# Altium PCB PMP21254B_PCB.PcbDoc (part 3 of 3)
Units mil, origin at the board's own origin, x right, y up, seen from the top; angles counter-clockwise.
Board outline 5000 x 7000 mil, 8 copper layers (Top Layer, Signal Layer 1, Signal Layer 2, Signal Layer 3, Signal Layer 4, Signal Layer 5, Signal Layer 6, Bottom Layer), stack 63 mil thick; 205 components, 78 nets, 623 pads, 1087 vias.
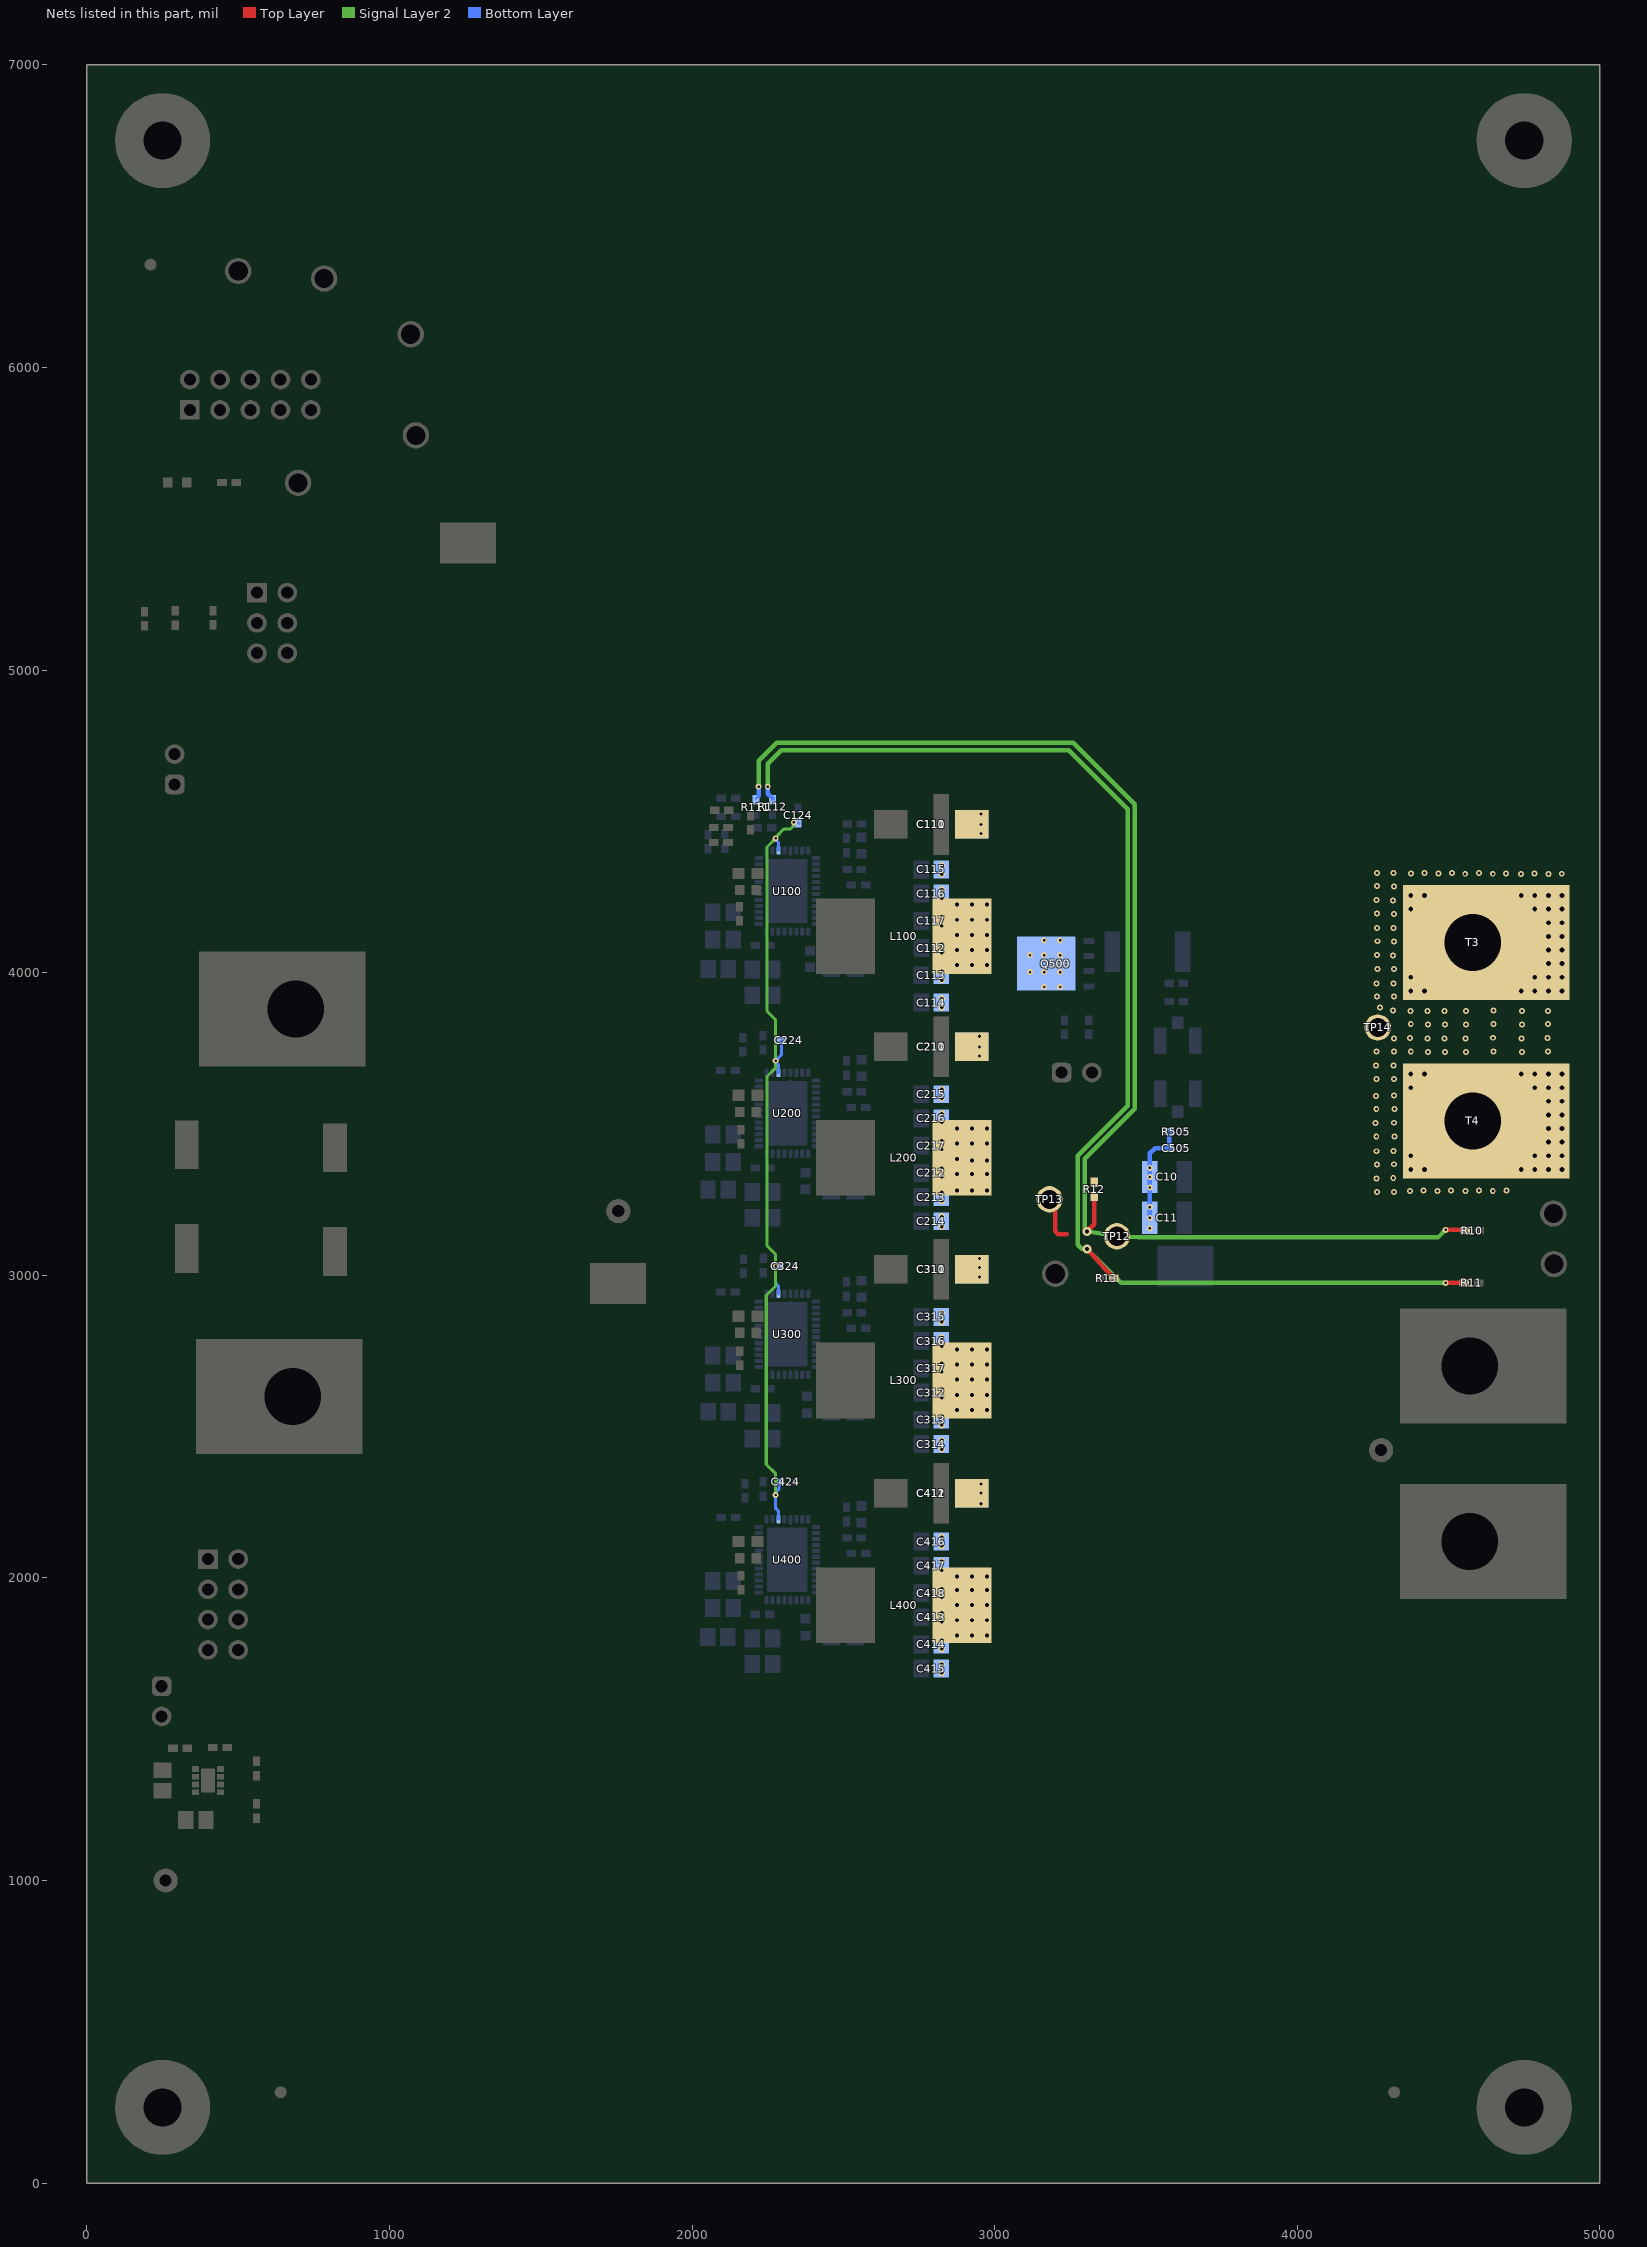
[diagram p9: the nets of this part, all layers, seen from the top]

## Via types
v1: diameter 19.68, hole 9.84, Top Layer to Bottom Layer, 427 vias
v2: diameter 22, hole 10, Top Layer to Bottom Layer, tented both sides, 225 vias
v3: diameter 30, hole 13, Top Layer to Bottom Layer, tented both sides, 171 vias
v4: diameter 32, hole 16, Top Layer to Bottom Layer, 168 vias
v5: diameter 19.68, hole 7.87, Top Layer to Bottom Layer, tented bottom, 35 vias
v6: diameter 19.68, hole 7.87, Top Layer to Bottom Layer, tented both sides, 27 vias
v7: diameter 19.68, hole 7.87, Top Layer to Bottom Layer, 22 vias
v8: diameter 22, hole 10, Top Layer to Bottom Layer, tented bottom, 6 vias
v9: diameter 19.68, hole 7.87, Top Layer to Bottom Layer, tented top, 5 vias
v10: diameter 19.68/19.68/19.68/19.68/19.68/19.68/19.68/19.68 (per signal layer), hole 7.87, Top Layer to Bottom Layer, tented both sides, 1 vias

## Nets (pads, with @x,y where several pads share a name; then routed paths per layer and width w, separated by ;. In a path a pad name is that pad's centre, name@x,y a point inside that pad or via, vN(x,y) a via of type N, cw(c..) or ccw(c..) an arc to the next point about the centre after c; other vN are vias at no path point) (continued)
Vout: C10.2 C11.2 C110.1 C111.1 C112.1 C113.1 C114.1 C115.1 C116.1 C117.1 C210.1 C211.1 C212.1 C213.1 C214.1 C215.1 C216.1 C217.1 C310.1 C311.1 C312.1 C313.1 C314.1 C315.1 C316.1 C317.1 C411.1 C412.1 C413.1 C414.1 C415.1 C416.1 C417.1 C418.1 C505.1 L100.2 L200.2 L300.2 L400.2 Q500.5 Q500.6 Q500.7 Q500.8 Q500.9@3170.09,4030 R12.1 R505.2 T3.1 T4.1 TP13.1 TP14.1 | length 445
  Top Layer w15: 3200,3210 3200,3145 3210,3135 3237.44,3135
  Bottom Layer w15: v5(3512.91,3190) v5(3512.91,3325) 3512.91,3402.91 3530,3420 C505.1@3576.38,3420 R505.2@3576.38,3475
  other v1: 4263.03,3275 4319.1,3276 4463,3278.03 4646,3278.03 4373,3279 4556,3279 4417,3280 4508,3280 4600,3280 4691,3280 4261.07,3320 4317.14,3321 4263.03,3366 4319.1,3367 4262.03,3410 4318.1,3411 4261,3458 4321,3459.1 4259.03,3503 4319.03,3504.1 4261,3549 4321,3550.1 4260,3593 4320,3594.1 4262,3648 4320,3648 4260.03,3693 4318.03,3693 4432,3738 4488,3738 4558,3738 4743,3738 4262,3739 4320,3739 4375,3739 4829,3739 4649,3740 4319,3783 4430.03,3783 4486.03,3783 4556.03,3783 4741.03,3783 4373.03,3784 4827.03,3784 4647.03,3785 4432,3829 4488,3829 4558,3829 4743,3829 4375,3830 4829,3830 4649,3831 4431,3873 4487,3873 4557,3873 4742,3873 4374,3874 4828,3874 4317.03,3875 4648,3875 4273,3885 4263,3921 4319,3921 4262,3965 4318,3965 4319,4012 4265,4013 4317.03,4057 4263.03,4058 4319,4103 4265,4104 4318,4147 4264,4148 4319,4194 4264,4195 4317.03,4239 4262.03,4240 4319,4285 4264,4286 4739,4326 4830,4326 4555,4326.97 4646,4326.97 4874,4327 4376,4327.93 4467,4327.93 4690,4327.97 4784,4327.97 4318,4329 4511,4328.93 4600,4328.93 4263,4330 4421,4329.9
  other v2: 2825,1685 2825,1715 2825,1765 2825,1795 2825,1855 2825,1885 2825,1935 2825,1965 2825,2025 2825,2055 2825,2105 2825,2135 2955,2245 2955,2280 2955,2310 2825,2425 2825,2455 2825,2505 2825,2535 2825,2595 2825,2625 2825,2680 2825,2710 2825,2765 2825,2795 2825,2845 2825,2875 2950,2995 2950,3025 2950,3055 2825,3160 2825,3195 2825,3245 2825,3275 2825,3325 2825,3355 2825,3415 2825,3445 2825,3505 2825,3535 2825,3585 2825,3615 2950,3725 2950,3755 2950,3790 2825,3885 2825,3915 2825,3975 2825,4005 2825,4065 2825,4095 2825,4155 2825,4185 2825,4245 2825,4275 2825,4325 2825,4355 2955,4460 2955,4490 2955,4525
  other v3: 2875,1810 2925,1810 2975,1810 2875,1860 2925,1860 2975,1860 2875,1910 2925,1910 2975,1910 2875,1960 2925,1960 2975,1960 2875,2005 2925,2005 2975,2005 2875,2555 2925,2555 2975,2555 2875,2605 2925,2605 2975,2605 2875,2655 2925,2655 2975,2655 2875,2705 2925,2705 2975,2705 2875,2755 2925,2755 2975,2755 2875,3280 2925,3280 2975,3280 2875,3335 2925,3335 2975,3335 2925,3380 2975,3380 2875,3385 2875,3435 2925,3435 2975,3435 2875,3485 2925,3485 2975,3485 2875,4025 2925,4025 2975,4025 2875,4075 2925,4075 2975,4075 2875,4125 2925,4125 2975,4125 2875,4175 2925,4175 2975,4175 2875,4225 2925,4225 2975,4225
  other v4: 4375,3350 4420,3350 4740,3350 4785,3350 4830,3350 4875,3350 4375,3395 4785,3395 4830,3395 4875,3395 4830,3440 4875,3440 4830,3485 4875,3485 4830,3530 4875,3530 4830,3575 4875,3575 4375,3620 4785,3620 4830,3620 4875,3620 4375,3665 4420,3665 4740,3665 4785,3665 4830,3665 4875,3665 4375,3940 4420,3940 4740,3940 4785,3940 4830,3940 4875,3940 4375,3985 4785,3985 4830,3985 4875,3985 4830,4030 4875,4030 4830,4075 4875,4075 4830,4120 4875,4120 4830,4165 4875,4165 4375,4210 4785,4210 4830,4210 4875,4210 4375,4255 4420,4255 4740,4255 4785,4255 4830,4255 4875,4255
  other v5: 3512.91,3155 3512.91,3225 3512.91,3290 3512.91,3355
  other v7: 3163.62,3952.83 3216.38,3952.83 3116.77,4001.85 3163.62,4001.85 3216.38,4001.85 3116.77,4058.15 3163.62,4058.15 3216.38,4058.15 3163.62,4107.17 3216.38,4107.17
VSH: C124.1 C224.1 C324.1 C424.1 U100.35 U200.35 U300.35 U400.35 | length 2728
  Signal Layer 2 w10: v5(2276,2274) 2276,2344 2245,2375 2245,2933.43 2276,2964.43 v5(2276,3030) 2276,3069 2247.13,3097.87 2247.13,3657.13 2276,3686 v7(2276,3709) 2276,3844 2247.13,3872.87 2247.13,4415.13 v7(2276,4444) 2276,4448.13 2302.87,4475 2325,4475 2336,4486 v5(2336,4497)
  Bottom Layer w10: v5(2276,3030) 2276,2974 2285.47,2964.53 U300.35@2285.47,2938.86 ; v7(2276,4444) 2276,4439.87 2285.47,4430.4 U100.35@2285.47,4403.86 ; U400.35@2285.47,2193.86 2285.47,2220.4 2276,2229.87 v5(2276,2274) 2276,2283 2286.38,2293.38 C424.1@2286.38,2317 ; U200.35@2285.47,3668.86 2285.47,3695.4 2276,3704.87 v7(2276,3709) 2295,3728 C224.1@2295,3776 ; C124.1@2350,4496.38 C124.1@2353,4493.38
VSNS_N: R11.2 R13.2 R112.1 | length 4376.2
  Top Layer w15: v3(3305,3087.56) R13.2@3393.62,2990 ; R13.2@3397.56,2990 R13.2@3397.56,2995 ; v9(4490,2975) R11.2@4543.5,2975
  Signal Layer 2 w15: v6(2250,4615) 2250,4690 2295,4735 3245,4735 3440,4540 3440,3560 3274.63,3394.63 3274.63,3100.37 3287.44,3087.56 v3(3305,3087.56) 3417.56,2975 v9(4490,2975)
  Bottom Layer w15: v6(2250,4615) 2250,4591.56 R112.1@2266,4575.56
VSNS_P: R10.1 R12.2 R111.1 TP12.1 | length 4389.2
  Top Layer w15: v3(3305,3145) 3329,3169 R12.2@3329,3260.86 ; TP12.1@3380,3115 TP12.1@3415,3150 ; v9(4490,3150) R10.1@4543.5,3150
  Signal Layer 2 w15: v6(2220,4615) 2220,4700 2280,4760 3260,4760 3462.87,4557.13 3462.87,3550.53 3297.5,3385.15 3297.5,3152.5 v3(3305,3145) TP12.1@3404,3129 3475,3125 4465,3125 v9(4490,3150)
  Bottom Layer w10: R111.1@2211,4575.56 R111.1@2220,4584.56
  Bottom Layer w15: R111.1@2220,4584.56 v6(2220,4615)
pads on no net: FID1.1 FID2.1 FID3.1 H1.1 H2.1 H3.1 H4.1 H5.0 H6.0 H7.0 H8.0 J2.1 J2.2 J2.3 J2.4 J500.2@3545.94,3775 J500.3@3664.06,3775 J501.2@3664.06,3600 J501.3@3545.94,3600 LBL1.0 Q500.9@3137.24,3973.7 Q500.9@3137.24,4030 Q500.9@3137.24,4086.3 Q500.9@3186.06,4030 Q500.9@3190,3973.7 Q500.9@3190,4030 Q500.9@3190,4086.3 Q500.9@3242.76,3973.7 Q500.9@3242.76,4030 Q500.9@3242.76,4086.3 U1.0 U1.7 U100.41@2282.91,4194.41 U100.41@2282.91,4244.8 U100.41@2282.91,4295.2 U100.41@2282.91,4345.59 U100.41@2347.09,4194.41 U100.41@2347.09,4244.8 U100.41@2347.09,4295.2 U100.41@2347.09,4345.59 U200.33 U200.41@2282.91,3459.41 U200.41@2282.91,3509.8 U200.41@2282.91,3560.2 U200.41@2282.91,3610.59 U200.41@2347.09,3459.41 U200.41@2347.09,3509.8 U200.41@2347.09,3560.2 U200.41@2347.09,3610.59 U300.33 U300.41@2282.91,2729.41 U300.41@2282.91,2779.8 U300.41@2282.91,2830.2 U300.41@2282.91,2880.59 U300.41@2347.09,2729.41 U300.41@2347.09,2779.8 U300.41@2347.09,2830.2 U300.41@2347.09,2880.59 U400.33 U400.41@2282.91,1984.41 U400.41@2282.91,2034.8 U400.41@2282.91,2085.2 U400.41@2282.91,2135.59 U400.41@2347.09,1984.41 U400.41@2347.09,2034.8 U400.41@2347.09,2085.2 U400.41@2347.09,2135.59
copper on no net:
  other v2: 3230,2205 3230,2310 1090,2645 1090,2780

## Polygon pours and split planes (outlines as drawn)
GND on Signal Layer 1 "SIGNAL_LAYER_1_GND_P027" (solid, remove dead copper, pour order 27): 0,-25 0,7010 4955,7010 4990,6975 4990,10
GND on Signal Layer 3 "SIGNAL_LAYER_3_GND_P031" (solid, remove dead copper, pour order 31): -25,0 -25,6960 25,7010 4975,7010 4975,25 5000,0
GND on Signal Layer 6 "SIGNAL_LAYER_6_GND_P041" (solid, remove dead copper, pour order 41): 10,25 0,35 0,7000 5010,7000 4975,6965 4975,-10
Vout on Signal Layer 4 "SIGNAL_LAYER_4_VOUT_P035" (solid, remove dead copper, pour order 35): 5000,977 5000,5176 2800,5176 2800,977
Vin on Signal Layer 4 "SIGNAL_LAYER_4_VIN_P051" (solid, remove dead copper, pour order 51): 0,1305 2215,1305 2215,5160 0,5160 0,3220 0,2355
GND on Signal Layer 4 "SIGNAL_LAYER_4_GND_P053" (solid, remove dead copper, pour order 53): 0,7000 5000,7000 5000,0 0,0 0,1275 2250,1275 2250,4900 0,4900
Vout on Top Layer "TOP_LAYER_VOUT_P023" (solid, remove dead copper, pour order 23): 2790,1655 2790,2160 2862.48,2160 2862.48,2397.48 2785,2397.48 2785,2907.32 2855,2907.32 2855,3140 2775,3140 2775,3643.44 2845,3643.44 2845,3870 2790,3870 2790,4374.92 2862.48,4374.92 2862.48,4600 3050,4600 3050,1655
Vout on Top Layer "TOP_LAYER_VOUT_P025" (solid, remove dead copper, pour order 25): 4997.69,999 4997.69,5171 2787.69,5171 2787.69,999
Vin on Top Layer "TOP_LAYER_VIN_P045" (solid, remove dead copper, pour order 45): -1.28,1306.06 2213.72,1306.06 2213.72,5161.06 -1.28,5161.06 -1.28,3221.06 1198.72,3221.06 1198.72,2356.06 -1.28,2356.06
GND on Top Layer "TOP_LAYER_GND_P047" (solid, remove dead copper, pour order 47): 0,2375 1175,2375 1175,3200 0,3200
GND on Top Layer "TOP_LAYER_GND_P055" (solid, remove dead copper, pour order 55): 0,7005 5000,7005 5000,0 0,0 0,1280 2250,1280 2250,4905 0,4905
Vout on Signal Layer 5 "SIGNAL_LAYER_5_VOUT_P039" (solid, remove dead copper, pour order 39): 5000,977 5000,5182 2800,5182 2800,977
Vin on Signal Layer 5 "SIGNAL_LAYER_5_VIN_P037" (solid, remove dead copper, pour order 37): 190,4460 1245,4460 2215,4460 2215,1325 190,1325 190,3230
GND on Signal Layer 5 "SIGNAL_LAYER_5_GND_P049" (solid, remove dead copper, pour order 49): 0,7000 5000,7000 5000,0 0,0 0,1275 2250,1275 2250,4900 0,4900
GND on Bottom Layer "BOTTOM_LAYER_GND_P043" (solid, remove dead copper, pour order 43): 5155.09,28.16 5155.09,7033.16 155.09,7033.16 155.09,28.16
GND on Signal Layer 2 "SIGNAL_LAYER_2_GND_P057" (solid, remove dead copper, pour order 57): 5000,0 5000,7005 0,7005 0,0

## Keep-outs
Keep-Out Layer:
  lines w20: -10,0 ccw(c0,0) 0,-10 ; -10,0 ccw(c0,0) 0,-10 ; -10,0 -10,7000 ; -10,7000 cw(c0,7000) 0,7010 ; -10,7000 cw(c0,7000) 0,7010 ; 0,-10 5000,-10 ; 0,7010 5000,7010 ; 5000,-10 ccw(c5000,0) 5010,0 ; 5000,-10 ccw(c5000,0) 5010,0 ; 5000,7010 cw(c5000,7000) 5010,7000 ; 5000,7010 cw(c5000,7000) 5010,7000 ; 5010,0 5010,7000 ; 10,10 4990,10 4990,6990 10,6990 10,10 ; 26.23,26.23 26.23,6973.77 4973.77,6973.77 4973.77,26.23 26.23,26.23
  text ".Layer_Name" at 577,-858.49 h60

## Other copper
Top Layer:
  rectangle net 5.3V: 363,1155 465,1270
  rectangle net GND: 2197,4304 2275,4393.88
  rectangle net GND: 2200,3577 2282,3613
  rectangle net GND: 2201,2849 2265,2882.58
  rectangle net GND: 2198,2102.26 2275,2137.85
  text ".Layer_Name" at 577,-858.49 h60
Signal Layer 6:
  rectangle net GND: 2260.39,1942 2383,2078
  rectangle net GND: 2260.47,2702.4 2295,2785
  rectangle net GND: 2266,4145 2372,4230.49
  rectangle net GND: 2250.45,3435 2275,3499.01
  rectangle net GND: 2034.8,4075 2172.72,4235
  rectangle net GND: 2035,3335.63 2170,3503.1
  rectangle net GND: 2035,2610 2169.65,2770
  rectangle net GND: 2032.52,1870 2170,2029.37
Bottom Layer:
  rectangle net GND: 2245,1905 2385,1960
  rectangle net GND: 2246.1,2650 2383.9,2705
  rectangle net GND: 2246.1,3376 2383.9,3440
  rectangle net GND: 2245,4120 2383.57,4175
  rectangle net Vout: 3485,3220 3540,3320
  rectangle net Vout: 2795,3870 3265,4375
  rectangle net NetC500_1: 3295,3995 3415,4135.94
  rectangle net NetC422_2: 2511,2170 2548,2199
  rectangle net F3_BP1V5: 2515,2222 2551,2249
  rectangle net L_BP1V5: 2510,4430 2555,4460
  rectangle net F1_BP1V5: 2510,3697 2549,3728
  rectangle net F2_BP1V5: 2515,2970 2550,2995
  rectangle net NetC109_1: 2370,3975 2579.37,4040
  rectangle net NetC209_1: 2360,3240 2574.37,3305
  rectangle net NetC309_1: 2360,2505 2575,2570
  region net Vin: 2230,4245 2110,4245 2110,4070 2094.92,4054.92 2094.92,3885 2230,3885
  region net Vin: 2230,3510 2230,3160 2228.52,3158.52 2090,3158.52 2090,3240 2104.45,3240 2104.45,3326.62 2104.45,3507.34 2105,3507.89
  region net Vin: 2230,2780 2230,2423.03 2104,2423.03 2104,2429 2104,2502.4 2104,2780
  region net GND: 2405.06,1885 2405.06,1840 2345,1840 2345,1680 2240,1680 2240,1885
  region net GND: 2400,2630 2400,2580 2350,2580 2350,2415 2240,2415 2240,2630
  region net GND: 2390,3365 2390,3320 2345,3320 2345,3160 2240,3160 2240,3365
  region net GND: 2410,4095 2410,4055 2355,4055 2355,3890 2245,3890 2245,4095
  region net NetC408_2: 2605,2035 2605,1840 2415,1840 2416.38,1841.38 2416.38,1950 2400,1950 2400,2035
  region net NetC308_2: 2400,2780 2605,2780 2605,2580 2416.38,2580 2416.38,2690 2400,2690
  region net NetC208_2: 2399.68,3510 2604.68,3510 2604.68,3315 2405.31,3315 2405.31,3425.26 2399.94,3425.26
  region net NetC108_2: 2398.64,4240 2605,4240 2605,4050 2420,4050 2420,4160 2400.62,4160
  region net Vin: 2230,2035 2230,1680.63 2229.37,1680 2110,1680 2110,1759.37 2110,1849.37 2110,2035
  text ".Layer_Name" at 577,-858.49 h60

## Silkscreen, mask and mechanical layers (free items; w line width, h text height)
Top Overlay:
  region: 2682,343 2382,343 2382,243 2682,243
  lines w10: 3000,1600 2000,1600 2000,4600 3000,4600 3000,1610
  text "Gnd" at 400,6240 h72.83 r90
  text "SMB_ALERT" at 670,6210 h72.83 r90
  text "PMBus Communications" at 180,6120 h72.83
  text "DATA" at 1012,5975 h72.83
  text "CLK" at 1020,5860 h72.83
  text "Cntl" at 800,5620 h72.83
  text "GND" at 1389,5411 h72.83
  text "Enable Choices" at 613,5339 h72.83
  text "PMBus CNTL" at 730,5240 h72.83
  text "UVLO" at 738,5107.63 h72.83
  text "UVLO divider" at 80,5050 h72.83
  text "Off" at 736,5026 h72.83
  text "All parts outside box are Test Interface" at 1820,4810 h110
  text "Actual design inside 1 inch by 4 inch box" at 1730,4720 h120
  text "Power Good" at 381,4698 h90
  text "Gnd" at 364,4590 h72.83
  text "Vin +" at 500,4140 h180
  text "Leader" at 1342,4089 h150
  text "Vout" at 4310,3980 h150 r90
  text "VOUT" at 4346,3791 h90
  text "Follower_1" at 1349,3524.97 h100
  text "Main Load +" at 4170,3415 h180 r90
  text "Vout" at 4310,3410 h150 r90
  text "Bode_Vout" at 3052,3344 h72.83
  text "RemoteSense+" at 4299,3208 h72.83
  text "VIN" at 1579,3191 h72.83
  text "Bode_Injection" at 3484,3083.47 h72.83
  text "RemoteSense-" at 4305,3030 h72.83
  text "GND" at 1494,2952.92 h72.83
  text "damping input caps" at 230,2890 h90
  text "Bode_Gnd" at 3045,2885 h72.83
  text "Follower_2" at 1388,2634 h100
  text "Ground" at 4300,2490 h150 r90
  text "GND" at 4346,2362 h90
  text "Vin Return" at 129,2244 h150
  text "---5.3V----" at 273,2085 h90 r270
  text "avin_l" at 580,2050 h72.83
  text "avin_f1" at 580,1940 h72.83
  text "Ground" at 4320,1910 h150 r90
  text "Main Load Rtn" at 4170,1900 h180 r90
  text "Follower_3" at 1405,1892 h100
  text "avin_f2" at 570,1840 h72.83
  text "avin_f3" at 570,1740 h72.83
  text "Bias Enable (5.3V)" at 331.49,1577 h90
  text "A" at 1570,1463.66 h182.5
  text "c" at 1658.24,1463.66 h182.5
  text "t" at 1723.18,1463.66 h182.5
  text "u" at 1774.79,1463.66 h182.5
  text "a" at 1854.71,1463.66 h182.5
  text "l" at 1927.97,1463.66 h182.5
  text "d" at 1997.9,1463.66 h182.5
  text "e" at 2077.82,1463.66 h182.5
  text "s" at 2154.41,1463.66 h182.5
  text "i" at 2214.35,1463.66 h182.5
  text "g" at 2249.32,1463.66 h182.5
  text "n" at 2320.91,1463.66 h182.5
  text "i" at 2435.8,1463.66 h182.5
  text "n" at 2470.76,1463.66 h182.5
  text "s" at 2550.68,1463.66 h182.5
  text "i" at 2610.62,1463.66 h182.5
  text "d" at 2645.59,1463.66 h182.5
  text "e" at 2725.51,1463.66 h182.5
  text "1" at 2835.4,1463.66 h182.5
  text "i" at 2948.62,1463.66 h182.5
  text "n" at 2983.58,1463.66 h182.5
  text "c" at 3063.5,1463.66 h182.5
  text "h" at 3128.44,1463.66 h182.5
  text "b" at 3241.66,1463.66 h182.5
  text "y" at 3321.58,1463.66 h182.5
  text "4" at 3426.47,1463.66 h182.5
  text "i" at 3539.69,1463.66 h182.5
  text "n" at 3574.65,1463.66 h182.5
  text "c" at 3654.57,1463.66 h182.5
  text "h" at 3719.51,1463.66 h182.5
  text "b" at 3832.73,1463.66 h182.5
  text "o" at 3912.65,1463.66 h182.5
  text "x" at 3994.23,1463.66 h182.5
  text "5.3V" at 347,960 h90
  text "Vin to 5.3V converter" at 70,820 h120
  text "'.PRJ_Number'.PCB_Rev-" at 1791,264 h108.27
  text ".Layer_Name" at 577,-858.49 h60
Bottom Overlay:
  lines w10: 2990,1600 2000,1600 2000,4600 3000,4600 3000,1600
  text "All parts outside box are Test Interface" at 3355,5040 h110
  text "Actual design inside 1 inch by 4 inch box" at 3518,4935 h120
  text "Isense" at 3887,3783 h80
  text "sig injection" at 3435,3729 h72.83 r90
  text "Vsense" at 3904,3600 h72.83
  text "GND" at 3814,3094.23 h72.83 r90
  text "Actual design inside 1 inch by 4 inch box" at 3530,1490 h120
  text ".Layer_Name" at 577,-858.49 h60
Top Paste:
  text ".Layer_Name" at 577,-858.49 h60
Bottom Paste:
  text ".Layer_Name" at 577,-858.49 h60
Top Solder:
  text ".Layer_Name" at 577,-858.49 h60
  text ".Layer_Name" at 577,-858.49 h60
Bottom Solder:
  text ".Layer_Name" at 577,-858.49 h60
Drill Guide:
  text ".Layer_Name" at 577,-858.49 h60
M1 Board Outline:
  the board outline again, w10
  text ".Layer_Name" at 577,-858.49 h60
M2 Board Dimensions:
  rectangle: 125,-400 500,-275
  rectangle: 0,-275 125,-150
  lines w7: 0,-275 1000,-275 ; 125,-400 125,-150 ; 250,-400 250,-150 ; 500,-400 500,-150 ; 750,-400 750,-150 ; 0,-400 0,-150 1000,-150 1000,-400 0,-400
  text ".Layer_Name" at 577,-858.49 h60
M3 3D STEP Top:
  text ".Layer_Name" at 577,-858.49 h60
M4 3D STEP Bottom:
  text ".Layer_Name" at 577,-858.49 h60
M5 Assembly Top:
  lines w10: -292,-930.17 6308,-930.17 ; -292,-726.83 6310,-726.83 ; -292,-523.5 -292,-1133.5 3713,-1133.5 6310,-1133.5 6310,-523.5 -291.5,-523.5 -291.5,-1133.5 1284,-1133.5 ; 2173,-1133.5 2173,-523.5 ; 3440,-726.83 3440,-523.5 ; 4280,-726.83 4280,-523.5 ; 4902,-1140 4902,-937.17
  text "COMPONENTS MARKED 'DNP' SHOULD NOT BE POPULATED." at 1153.5,-318.5 h60
  text "ASSEMBLY VARIANT:" at 1153,-434 h60
  text ".VariantName" at 2189,-434 h60
  text "PCB VIEWED FROM TOP SIDE" at -228.5,-655.67 h60
  text "BOARD #:" at 2248,-655.67 h60
  text ".PRJ_Number" at 2793.5,-655.67 h60
  text "REV:" at 3638,-655.67 h60
  text ".PCB_Rev" at 3929.5,-655.67 h60
  text "SVN REV:" at 4476,-655.67 h60
  text ".VersionControl_RevNumber" at 4982,-655.67 h60
  text "TID #:" at 2248,-859 h60
  text ".TID" at 2793.5,-859 h60
  text "PLOT NAME =" at -228.5,-1064.34 h60
  text ".plot_File_Name" at 577,-1064.34 h60
  text "GENERATED    :" at 2250,-1064.34 h60
  text ".Print_Date" at 3119.5,-1064.34 h60
  text ".Print_Time" at 3848.5,-1064.34 h60
  text "TEXAS INSTRUMENTS" at 5113,-1064.34 h60
M6 Assembly Bottom:
  lines w10: -292.5,-727.33 6309.5,-727.33 ; -290.5,-930.67 6309.5,-930.67 ; 1115.5,-1140.5 1115.5,-937.67 ; 1737.5,-727.33 1737.5,-524 ; 2577.5,-727.33 2577.5,-524 ; 3844.5,-1134 3844.5,-524 ; 4733.5,-1134 6309,-1134 6309,-524 -292.5,-524 -292.5,-1134 2304.5,-1134 6309.5,-1134 6309.5,-524
  text "COMPONENTS MARKED 'DNP' SHOULD NOT BE POPULATED." at 6102,-318 h60
  text ".VariantName" at 5058,-434 h60
  text "ASSEMBLY VARIANT:" at 6097,-434 h60
  text ".VersionControl_RevNumber" at 1035.5,-656.17 h60
  text "SVN REV:" at 1541.5,-656.17 h60
  text ".PCB_Rev" at 2088,-656.17 h60
  text "REV:" at 2379.5,-656.17 h60
  text ".PRJ_Number" at 3224,-656.17 h60
  text "BOARD #:" at 3769.5,-656.17 h60
  text "PCB VIEWED FROM BOTTOM SIDE" at 6246,-656.17 h60
  text ".TID" at 3224,-859.5 h60
  text "TID #:" at 3769.5,-859.5 h60
  text "TEXAS INSTRUMENTS" at 904.5,-1064.84 h60
  text ".Print_Time" at 2169,-1064.84 h60
  text ".Print_Date" at 2898,-1064.84 h60
  text "GENERATED    :" at 3767.5,-1064.84 h60
  text ".plot_File_Name" at 5440.5,-1064.84 h60
  text "PLOT NAME =" at 6246,-1064.84 h60
M9 Title Sheet:
  drawing of 57 lines, arcs and shapes, not listed
  text "1" at 739.84,8036.5 h70
  text "2" at 3235.5,8036.5 h70
  text "3" at 5724.84,8036.5 h70
  text "4" at 8231.51,8036.5 h70
  text "5" at 10730.5,8036.5 h70
  text "6" at 13235.5,8036.5 h70
  text "A" at -416.5,6893.5 h70
  text "A" at 14383.5,6893.5 h70
  text "B" at -416.5,4513.5 h70
  text "B" at 14383.5,4513.5 h70
  text "C" at -416.5,2138.5 h70
  text "C" at 14383.5,2138.5 h70
  text "PROJECT TITLE:" at 11343.5,277.5 h45
  text ".PRJ_Title" at 11393.5,144.17 h70
  text "DESIGNED FOR:" at 11343.5,-23.5 h45
  text ".PRJ_Customer" at 11393.5,-163.5 h70
  text "D" at -416.5,-231.5 h70
  text "D" at 14383.5,-231.5 h70
  text "FILE NAME:" at 11343.5,-323.5 h45
  text ".PCB_File_Name_No_Path" at 11393.5,-443.5 h70
  text "Texas Instruments (TI) and/or its licensors do not warrant the accuracy or completeness of this specification" at 6374,-605.34 h45
  text "ENGINEER:" at 11343.5,-613.5 h45
  text "LAYOUT BY:" at 12848.5,-613.5 h45
  text "or any information contained therein. TI and/or its licensors do not warrant that this design will meet" at 6329.01,-718 h45
  text ".PRJ_Engineer" at 11393.5,-768.49 h70
  text ".PCB_Layout" at 12899,-768.49 h70
  text "the specifications, will be suitable for your application or fit for any particular purpose, or will operate in" at 6329.01,-830.67 h45
  text ".Layer_Name" at 577,-858.49 h60
  text "ALTIUM DESIGNER VERSION:" at 12848.5,-923.5 h45
  text "an implementation. TI and/or its licensors do not warrant that the design is production worthy. You should" at 6329.01,-943.33 h45
  text "completely validate and test your design implementation to confirm the system functionality for your application." at 6374,-1056 h45
  text ".print_Scale" at 11393.5,-1056.83 h70
  text ".Application_BuildNumber" at 12899,-1056.83 h70
  text "1" at 739.84,-1263.5 h70
  text "2" at 3235.5,-1263.5 h70
  text "3" at 5724.84,-1263.5 h70
  text "4" at 8231.51,-1263.5 h70
  text "5" at 10730.5,-1263.5 h70
  text "6" at 13235.5,-1263.5 h70
M10 Fab Notes:
  drawing of 189 lines, arcs and shapes, not listed
  text "DESIGN INFORMATION" at 12382.02,6356.17 h60
  text "MIN. TRACK WIDTH:" at 11737.46,6224.05 h60
  text "8" at 12833.7,6224.05 h60
  text "MIL" at 12988.46,6224.05 h60
  text "5.906" at 12665,6105 h60
  text "MIN. CLEARANCE:" at 11737.46,6099.92 h60
  text "MIL" at 12988.46,6099.92 h60
  text "MIN. VIA PAD SIZE:" at 11737.46,5975.8 h60
  text "24" at 12803.71,5975.8 h60
  text "MIL" at 12988.46,5975.8 h60
  text "0.05mm (2MIL)" at 12432.46,5845.9 h60
  text "MINIMUM ANNULAR RING" at 11408.23,5837.67 h60
  text "EXTERNAL" at 13140.46,5837.67 h60
  text "PER" at 11608.23,5727.55 h60
  text "IPC-D-275 CLASS 2 LEVEL C" at 11828.23,5727.54 h60
  text "MIL, HOLES" at 13316.46,5627.07 h60
  text "+/-" at 12924,5618.48 h60
  text "+/-" at 13778,5618.48 h60
  text "REGISTRATION TOLERANCES:" at 11408.23,5617.42 h60
  text "METAL" at 12608,5617.42 h60
  text "5" at 13184.2,5617.42 h60
  text "3" at 14017.2,5617.42 h60
  text "MIL" at 14133.46,5617.42 h60
  text "HOLE SIZE TOLERANCE (UNLESS OTHERWISE SPECIFIED):" at 11408.23,5519.1 h60
  text "+/-" at 13778,5516.23 h60
  text "3" at 14017.2,5515.17 h60
  text "MIL" at 14133.46,5515.17 h60
  text "MATERIAL:" at 11333.46,5377.52 h60
  text "FR-4 High Tg" at 12319.9,5249 h60
  text "X" at 12175.46,5241.01 h60
  text "FR-408" at 11754.46,5236.49 h60
  text "OTHER" at 13242.46,5236.49 h60
  text "62 MIL (1.6mm) +/-10%" at 12074.56,5093.46 h60
  text "X" at 11954.46,5091.01 h60
  text "THICKNESS:" at 11408.23,5085.24 h60
  text "OTHER" at 13359.46,5085.24 h60
  text "TOLERANCE:" at 11408.23,4946.92 h60
  text "X" at 12256.46,4946.92 h60
  text "ANSI IPC-6012 TYPE 3 CLASS 2" at 12434.48,4946.92 h60
  text "OTHER +/-" at 12434.46,4802.73 h60
  text "BOW & TWIST:" at 11408.23,4657.54 h60
  text "X" at 12256.46,4657.54 h60
  text "ANSI IPC-6012 TYPE 3 CLASS 2" at 12434.48,4657.54 h60
  text "OTHER +/-" at 12434.46,4510.85 h60
  text "DRILLING:" at 11333.46,4380.23 h60
  text "NC_DRILL FILES" at 13094.46,4275.04 h60
  text "REFERENCE:" at 11408.23,4271.1 h60
  text "X" at 12065.46,4271.01 h60
  text "AS SHOWN" at 12243.46,4271.1 h60
  text "X" at 12966.46,4271.1 h60
  text "OTHER" at 13392.46,4128.85 h60
  text "PTH COPPER THICKNESS:" at 11407.91,4125.32 h60
  text "X" at 12547.14,4125.32 h60
  text "20-30 um" at 12675.14,4125.32 h60
  text "BOARD FINISH:" at 11333.46,3977.73 h60
  text "SILKSCREEN:" at 11488.68,3867.6 h60
  text "X" at 12446.46,3867.6 h60
  text "TOP" at 12563.46,3867.6 h60
  text "X" at 12956.46,3867.6 h60
  text "BOTTOM" at 13074.46,3867.6 h60
  text "SILKSCREEN COLOR:" at 11488.68,3712.41 h60
  text "X" at 12445.46,3712.41 h60
  text "WHITE" at 12563.46,3712.41 h60
  text "OTHER" at 13074.46,3712.41 h60
  text "X" at 12576.46,3568.96 h60
  text "GREEN" at 12694.46,3568.96 h60
  text "OTHER" at 13312.46,3568.96 h60
  text "SOLDER RESIST COLOR:" at 11488.68,3562.1 h60
  text "X" at 12576.46,3414.71 h60
  text "MATTE" at 12694.46,3414.71 h60
  text "SEMI-GLOSS" at 13312,3414.07 h60
  text "IMMERSION GOLD (ENIG)" at 12394.46,3241.94 h60
  text "ENEPIG" at 13732,3234.72 h60
  text "SURFACE FINISH:" at 11333.46,3233.72 h60
  text "X" at 12216.46,3233.72 h60
  text "IMM. TIN/SILVER OR EQUIV" at 11663,3096.4 h60
  text "OTHER" at 13094.46,3092.47 h60
  text "ARRAY/PANEL:" at 11333.46,2937.09 h60
  text "X" at 12220,2935 h60
  text "CUT AND TRIM PER M1 BOARD OUTLINE" at 12394.46,2928.87 h60
  text "N.C. ROUTE" at 12394.46,2792.9 h60
  text "V. SCORE" at 13260.46,2792.9 h60
  text "CERTIFICATION:" at 11333.46,2663.77 h60
  text "MATERIALS AND WORKMANSHIP FOR ALL PCBS" at 12058.46,2663.77 h60
  text "TO MEET OR EXCEED THE REQUIREMENTS OF:" at 12058.46,2569.71 h60
  text "X" at 11695.97,2441.08 h60
  text "ANSI IPC-A-600F CLASS ->" at 11823.96,2441.08 h60
  text "X" at 13471.97,2441.08 h60
  text "2" at 13581.96,2441.08 h60
  text "1" at 13266.96,2439.58 h60
  text "3" at 13935.96,2439.58 h60
  text "X" at 12507.97,2293.39 h60
  text "RoHS" at 12635.96,2293.39 h60
  text "OTHER" at 13280.36,2293.39 h60
  text "PER ORDER" at 13677.42,2293.39 h60
  text "ALL BOARDS MUST MEET OR EXCEED UL94-V0 REQUIREMENTS." at 11361,2139.57 h60
  text "PCB MUST BEAR THE UL94V-0 UL REGISTERED MATERIAL ID NUMBER" at 11361,2023.5 h60
  text "ADDITIONAL REQUIREMENTS:" at 11333.46,1854.08 h60
  text "MICROSECTION:" at 11408.23,1746.95 h60
  text "YES" at 12313.96,1746.95 h60
  text "REQUIRED" at 13175.46,1602.62 h60
  text "BARE BOARD ELEC. TEST:" at 11408.23,1599.76 h60
  text "NONE" at 12713.96,1599.76 h60
  text "X" at 13057.46,1599.76 h60
  text "PER ORDER" at 13767.46,1599.76 h60
  text "XX MIL VIAS REQUIRE NON-CONDUCTIVE FILL AND PLANARIZE" at 11576.38,1394.82 h59
  text "XX MIL VIAS REQUIRE CONDUCTIVE FILL AND PLANARIZE" at 11584.38,1290.84 h60
  text "OUTER XX MIL VIAS REQUIRE 50 OHM SINGLE-ENDED IMPEDANCE" at 11583.39,1127.46 h58
  text "LAYER 2 & 3 (INNER LAYERS) XX MIL WIDE, XX MIL SPACE / TRACES REQUIRE 100 OHM DIFFERENTIAL IMPEDANCE" at 11575.39,891.74 h60
  text ".Layer_Name" at 577,-858.49 h60
M11 Gerber Information:
  lines w10: -292,-930.17 6308,-930.17 ; -292,-726.83 6310,-726.83 ; -292,-523.5 -292,-1133.5 3713,-1133.5 6310,-1133.5 6310,-523.5 -291.5,-523.5 -291.5,-1133.5 1284,-1133.5 ; 2173,-1133.5 2173,-523.5 ; 3440,-726.83 3440,-523.5 ; 4280,-726.83 4280,-523.5 ; 4902,-1140 4902,-937.17
  text "ALL ARTWORK VIEWED FROM TOP SIDE" at -228.5,-655.67 h60
  text "BOARD #:" at 2248,-655.67 h60
  text ".PRJ_Number" at 2793.5,-655.67 h60
  text "REV:" at 3638,-655.67 h60
  text ".PCB_Rev" at 3929.5,-655.67 h60
  text "SVN REV:" at 4476,-655.67 h60
  text ".VersionControl_RevNumber" at 4982,-655.67 h60
  text "LAYER NAME =" at -228.5,-858.49 h60
  text "TID #:" at 2248,-859 h60
  text ".TID" at 2793.5,-859 h60
  text "PLOT NAME =" at -228.5,-1064.34 h60
  text ".plot_File_Name" at 577,-1064.34 h60
  text "GENERATED    :" at 2250,-1064.34 h60
  text ".Print_Date" at 3119.5,-1064.34 h60
  text ".Print_Time" at 3848.5,-1064.34 h60
  text "TEXAS INSTRUMENTS" at 5113,-1064.34 h60
M12 Stackup:
  drawing of 503 lines, arcs and shapes, not listed
  text "Layer" at 5710.74,7520 h60
  text "Name" at 6120.66,7520 h60
  text "Material" at 7060.4,7520 h60
  text "Thickness" at 7920.16,7520 h60
  text "Constant" at 8570,7520 h60
  text "Board Layer Stack" at 9139.86,7520 h60
  text "1" at 5710.74,7400 h60
  text "Top Overlay" at 6120.66,7400 h60
  text "2" at 5710.74,7280 h60
  text "Top Solder" at 6120.66,7280 h60
  text "Solder Resist" at 7060.4,7280 h60
  text "0.40mil" at 7920.16,7280 h60
  text "3.5" at 8570,7280 h60
  text "3" at 5710.74,7160 h60
  text "Top Layer" at 6120.66,7160 h60
  text "Copper" at 7060.4,7160 h60
  text "2.10mil" at 7920.16,7160 h60
  text "4" at 5710.74,7040 h60
  text "Dielectric1" at 6120.66,7040 h60
  text "FR-4" at 7060.4,7040 h60
  text "6.00mil" at 7920.16,7040 h60
  text "4.8" at 8570,7040 h60
  text "5" at 5710.74,6920 h60
  text "Signal Layer 1" at 6120.66,6920 h60
  text "Copper" at 7060.4,6920 h60
  text "2.80mil" at 7920.16,6920 h60
  text "6" at 5710.74,6800 h60
  text "Dielectric 2" at 6120.66,6800 h60
  text "6.00mil" at 7920.16,6800 h60
  text "4.2" at 8570,6800 h60
  text "7" at 5710.74,6680 h60
  text "Signal Layer 2" at 6120.66,6680 h60
  text "Copper" at 7060.4,6680 h60
  text "2.80mil" at 7920.16,6680 h60
  text "8" at 5710.74,6560 h60
  text "Dielectric 3" at 6120.66,6560 h60
  text "6.00mil" at 7920.16,6560 h60
  text "4.2" at 8570,6560 h60
  text "9" at 5710.74,6440 h60
  text "Signal Layer 3" at 6120.66,6440 h60
  text "Copper" at 7060.4,6440 h60
  text "2.80mil" at 7920.16,6440 h60
  text "10" at 5710.74,6320 h60
  text "Dielectric 4" at 6120.66,6320 h60
  text "6.00mil" at 7920.16,6320 h60
  text "4.2" at 8570,6320 h60
  text "11" at 5710.74,6200 h60
  text "Signal Layer 4" at 6120.66,6200 h60
  text "Copper" at 7060.4,6200 h60
  text "2.80mil" at 7920.16,6200 h60
  text "12" at 5710.74,6080 h60
  text "Dielectric 5" at 6120.66,6080 h60
  text "6.00mil" at 7920.16,6080 h60
  text "4.2" at 8570,6080 h60
  text "13" at 5710.74,5960 h60
  text "Signal Layer 5" at 6120.66,5960 h60
  text "Copper" at 7060.4,5960 h60
  text "2.80mil" at 7920.16,5960 h60
  text "14" at 5710.74,5840 h60
  text "Dielectric 6" at 6120.66,5840 h60
  text "6.00mil" at 7920.16,5840 h60
  text "4.2" at 8570,5840 h60
  text "15" at 5710.74,5720 h60
  text "Signal Layer 6" at 6120.66,5720 h60
  text "Copper" at 7060.4,5720 h60
  text "2.80mil" at 7920.16,5720 h60
  text "16" at 5710.74,5600 h60
  text "Dielectric 7" at 6120.66,5600 h60
  text "6.00mil" at 7920.16,5600 h60
  text "4.2" at 8570,5600 h60
  text "17" at 5710.74,5480 h60
  text "Bottom Layer" at 6120.66,5480 h60
  text "Copper" at 7060.4,5480 h60
  text "2.10mil" at 7920.16,5480 h60
  text "18" at 5710.74,5360 h60
  text "Bottom Solder" at 6120.66,5360 h60
  text "Solder Resist" at 7060.4,5360 h60
  text "0.40mil" at 7920.16,5360 h60
  text "3.5" at 8570,5360 h60
  text "19" at 5710.74,5240 h60
  text "Bottom Overlay" at 6120.66,5240 h60
  text ".Layer_Name" at 577,-858.49 h60
M13 Component Bodies Top:
  text ".Layer_Name" at 577,-858.49 h60
M14 Component Bodies Bottom:
  text ".Layer_Name" at 577,-858.49 h60
M15 Courtyards Top:
  text ".Layer_Name" at 577,-858.49 h60
M16 Courtyards Bottom:
  text ".Layer_Name" at 577,-858.49 h60
Drill Drawing:
  circle w10: c6088.72,3441.32 r27.63
  circle w10: c6088.72,2944.04 r16.58
  circle w10: c6088.72,2944.04 r27.63
  lines w10: 6061.09,2792.1 6088.72,2805.91 6116.34,2792.1 6102.53,2819.72 6116.34,2847.35 6088.72,2833.54 6061.09,2847.35 6074.9,2819.72 6061.09,2792.1 ; 6061.09,3040.74 6116.34,3040.74 6116.34,3095.99 6061.09,3095.99 6061.09,3040.74 ; 6061.09,3220.31 6116.34,3220.31 6088.72,3165.06 6061.09,3220.31 ; 6061.09,3303.19 6074.9,3303.19 6074.9,3289.38 6102.53,3289.38 6102.53,3303.19 6116.34,3303.19 6116.34,3330.82 6102.53,3330.82 6102.53,3344.63 6074.9,3344.63 6074.9,3330.82 6061.09,3330.82 6061.09,3303.19 ; 6061.09,3565.64 6088.72,3538.02 6116.34,3565.64 6088.72,3593.27 6061.09,3565.64 ; 6061.09,3662.34 6116.34,3662.34 6116.34,3717.59 6061.09,3717.59 6061.09,3662.34 ; 6061.09,3786.66 6061.09,3800.47 6074.9,3814.28 6061.09,3828.1 6061.09,3841.91 6074.9,3841.91 6088.72,3828.1 6102.53,3841.91 6116.34,3841.91 6116.34,3828.1 6102.53,3814.28 6116.34,3800.47 6116.34,3786.66 6102.53,3786.66 6088.72,3800.47 6074.9,3786.66 6061.09,3786.66 ; 6072.14,3673.39 6105.29,3673.39 6105.29,3706.54 6072.14,3706.54 6072.14,3673.39
  lines w12: 6011,2754.8 9242.49,2754.8 ; 6011,3873.68 9242.49,3873.68 ; 6348.86,2630.48 6348.86,3998 ; 6680.86,2630.48 6680.86,3998 ; 7317.43,2630.48 7317.43,3998 ; 7576.57,2630.48 7576.57,3998 ; 7951.72,2630.48 7951.72,3998 ; 8676.05,2630.48 8676.05,3998 ; 6011,2630.48 9242.49,2630.48 9242.49,3998 6011,3998 6011,2630.48
  text "Symbol" at 6085.59,3910.98 h72
  text "Quantity" at 6386.16,3910.98 h72
  text "Finished Hole Size" at 6718.16,3910.98 h72
  text "Plated" at 7354.72,3910.98 h72
  text "Hole Type" at 7613.86,3910.98 h72
  text "Drill Layer Pair" at 7989.02,3910.98 h72
  text "Hole Tolerance" at 8713.35,3910.98 h72
  text "90" at 6386.16,3786.66 h60
  text "7.87mil (0.200mm)" at 6718.16,3786.66 h60
  text "PTH" at 7354.72,3786.66 h60
  text "Round" at 7613.86,3786.66 h60
  text "Top Layer - Bottom Layer" at 7989.02,3786.66 h60
  text "427" at 6386.16,3662.34 h60
  text "9.84mil (0.250mm)" at 6718.16,3662.34 h60
  text "PTH" at 7354.72,3662.34 h60
  text "Round" at 7613.86,3662.34 h60
  text "Top Layer - Bottom Layer" at 7989.02,3662.34 h60
  text "231" at 6386.16,3538.02 h60
  text "10.00mil (0.254mm)" at 6718.16,3538.02 h60
  text "PTH" at 7354.72,3538.02 h60
  text "Round" at 7613.86,3538.02 h60
  text "Top Layer - Bottom Layer" at 7989.02,3538.02 h60
  text "171" at 6386.16,3413.7 h60
  text "13.00mil (0.330mm)" at 6718.16,3413.7 h60
  text "PTH" at 7354.72,3413.7 h60
  text "Round" at 7613.86,3413.7 h60
  text "Top Layer - Bottom Layer" at 7989.02,3413.7 h60
  text "168" at 6386.16,3289.38 h60
  text "16.00mil (0.406mm)" at 6718.16,3289.38 h60
  text "PTH" at 7354.72,3289.38 h60
  text "Round" at 7613.86,3289.38 h60
  text "Top Layer - Bottom Layer" at 7989.02,3289.38 h60
  text "33" at 6386.16,3165.06 h60
  text "40.00mil (1.016mm)" at 6718.16,3165.06 h60
  text "PTH" at 7354.72,3165.06 h60
  text "Round" at 7613.86,3165.06 h60
  text "Top Layer - Bottom Layer" at 7989.02,3165.06 h60
  text "11" at 6386.16,3040.74 h60
  text "63.00mil (1.600mm)" at 6718.16,3040.74 h60
  text "PTH" at 7354.72,3040.74 h60
  text "Round" at 7613.86,3040.74 h60
  text "Top Layer - Bottom Layer" at 7989.02,3040.74 h60
  text "4" at 6386.16,2916.42 h60
  text "125.98mil (3.200mm)" at 6718.16,2916.42 h60
  text "PTH" at 7354.72,2916.42 h60
  text "Round" at 7613.86,2916.42 h60
  text "Top Layer - Bottom Layer" at 7989.02,2916.42 h60
  text "6" at 6386.16,2792.1 h60
  text "188.00mil (4.775mm)" at 6718.16,2792.1 h60
  text "PTH" at 7354.72,2792.1 h60
  text "Round" at 7613.86,2792.1 h60
  text "Top Layer - Bottom Layer" at 7989.02,2792.1 h60
  text "1141 Total" at 6386.16,2667.78 h60
  text ".Layer_Name" at 577,-858.49 h60
M17 Embedded Cavity:
  text ".Layer_Name" at 577,-858.49 h60
M18 Embedded Assembly:
  text ".Layer_Name" at 577,-858.49 h60
M19 Embedded Keepout:
  text ".Layer_Name" at 577,-858.49 h60

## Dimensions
0,0 to 5000,0 on M2 Board Dimensions
0,0 to 0,7000 on M2 Board Dimensions
0,-400 to 1000,-400 on M2 Board Dimensions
